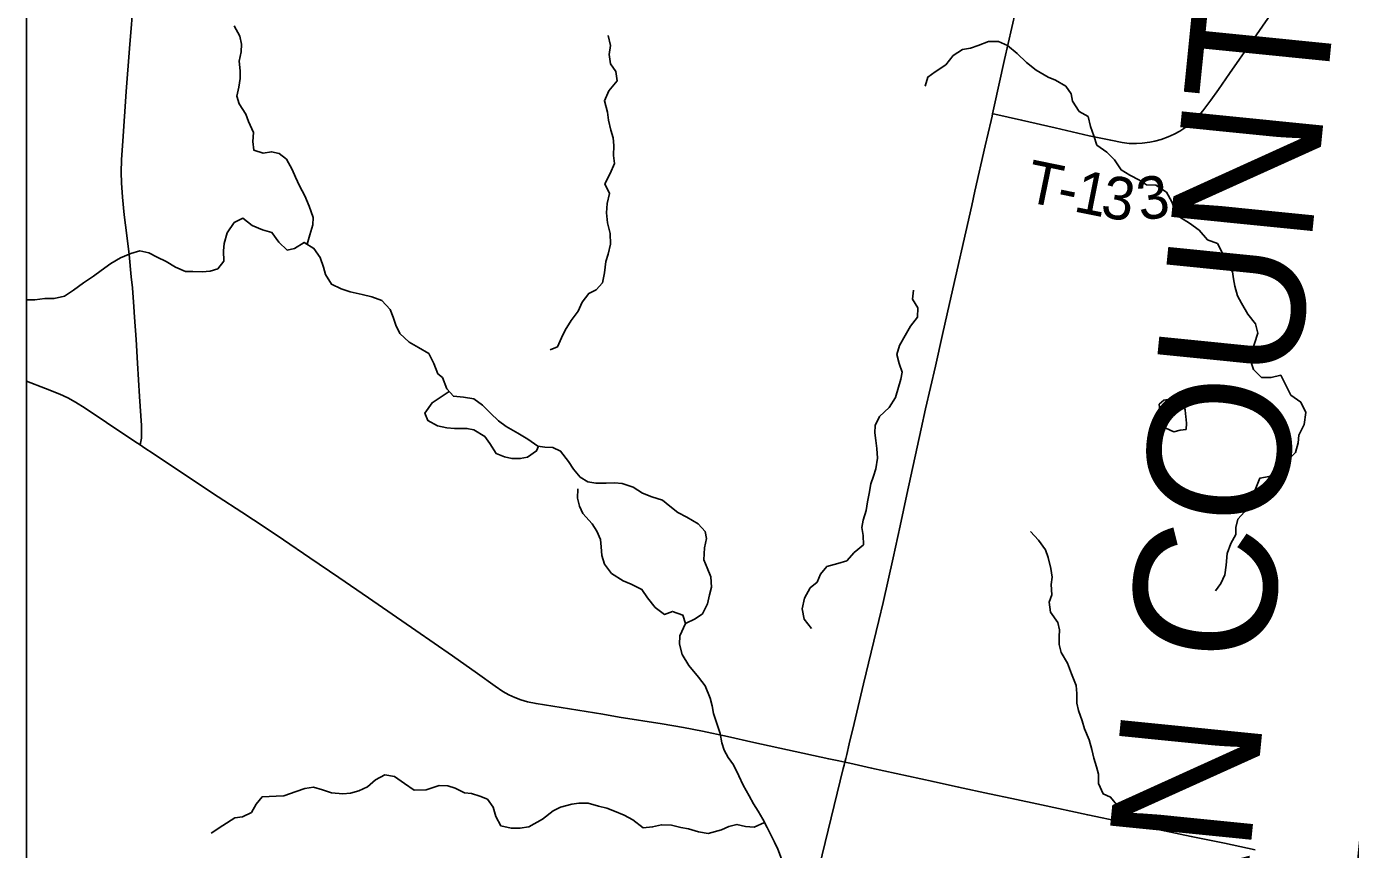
# Model space of a CAD drawing. Extents: x 0 to 34, y 0 to 22.
# Drawn here: x 2.1 to 2.983, y 17.069 to 17.618 of the extents above; entities that cross this region are included whole.
import ezdxf

# ---------------------------------------------------------------- set-up
doc = ezdxf.new("R2010")
doc.units = 0
for name, color, linetype in [('GM_X_Corporation', 7, 'Continuous'), ('GM_X_County_Road', 7, 'Continuous'), ('GM_X_County_Text', 7, 'Continuous'), ('GM_X_Minor_Lake', 7, 'Continuous'), ('GM_X_Minor_River', 7, 'Continuous'), ('GM_X_Township_Road', 7, 'Continuous'), ('GM_X_Township_Road_Text', 7, 'Continuous'), ('SH_Data', 7, 'Continuous')]:
    doc.layers.add(name, color=color, linetype=linetype)

msp = doc.modelspace()

# ---------------------------------------------------------------- linework, layer by layer
at = {"layer": 'GM_X_Corporation'}
msp.add_lwpolyline([(2.84444, 15.57923), (2.89388, 16.10066), (2.90694, 16.23807), (2.9254, 16.40612), (2.98802, 17.06029), (3.03309, 17.51715), (3.06374, 17.81635), (3.09312, 18.12631), (3.11125, 18.30141), (3.1559, 18.76858), (3.1859, 19.03952), (3.22871, 19.50287), (3.24175, 19.64034), (3.25924, 19.82357), (3.29526, 20.15731), (3.35748, 20.79083), (3.36874, 20.9), (2.1, 20.9), (2.1, 14.1)], dxfattribs=at)
msp.add_lwpolyline([(2.1, 18.2085), (2.1, 15.03648), (2.12001, 15.03535), (2.12058, 15.03531), (2.13937, 15.03437), (2.14359, 15.03416), (2.14799, 15.03391), (2.79096, 14.99744), (2.84444, 15.57923), (2.89388, 16.10066), (2.90694, 16.23807), (2.9254, 16.40612), (2.98802, 17.06029), (3.03309, 17.51715), (3.06374, 17.81635), (3.09312, 18.12631), (3.02521, 18.13347), (2.8083, 18.15094), (2.40932, 18.18308), (2.13113, 18.20548)], close=True, dxfattribs=at)
at = {"layer": 'GM_X_County_Road'}
for points in [[(2.646, 17.12758), (2.64664, 17.13014), (2.64729, 17.13271), (2.64891, 17.13983), (2.65233, 17.1535), (2.65855, 17.17984), (2.66879, 17.22211), (2.67158, 17.23422), (2.67824, 17.26393), (2.68289, 17.28518), (2.68747, 17.30613), (2.69687, 17.34986), (2.69984, 17.36321), (2.70644, 17.39185), (2.71106, 17.41291), (2.71586, 17.43349), (2.73069, 17.49888), (2.73282, 17.50844), (2.73952, 17.53879), (2.74354, 17.55552), (2.74419, 17.55846), (2.74455, 17.56011), (2.74542, 17.56404), (2.75258, 17.59636), (2.75994, 17.62834)], [(2.1, 17.38182), (2.11269, 17.37693), (2.12222, 17.37311), (2.12759, 17.3706), (2.1328, 17.36777), (2.13915, 17.36381), (2.15335, 17.35429), (2.17239, 17.34156), (2.17575, 17.33931), (2.17907, 17.3371), (2.1846, 17.3334), (2.21072, 17.31602), (2.22782, 17.3047), (2.24368, 17.29434), (2.25924, 17.28407), (2.27139, 17.27597), (2.28911, 17.26401), (2.30846, 17.25077), (2.32811, 17.23727), (2.35987, 17.21546), (2.38413, 17.19865), (2.40089, 17.18682), (2.41272, 17.17827), (2.41788, 17.17485), (2.42189, 17.17253), (2.42577, 17.17066), (2.42979, 17.16913), (2.43424, 17.1679), (2.44, 17.16675), (2.46238, 17.16311), (2.48447, 17.15956), (2.4955, 17.15773), (2.52402, 17.15314), (2.53843, 17.15074), (2.55094, 17.14829), (2.56766, 17.14472), (2.58525, 17.1408), (2.63532, 17.12984), (2.64203, 17.12842), (2.646, 17.12758), (2.6493, 17.12688), (2.66387, 17.12367), (2.70483, 17.11464), (2.72184, 17.11101), (2.74249, 17.10656), (2.75738, 17.1034), (2.77713, 17.09915), (2.80809, 17.09242), (2.83152, 17.08757), (2.85919, 17.08177), (2.87714, 17.07809), (2.89935, 17.07351), (2.91973, 17.06925)], [(2.62892, 17.05762), (2.64496, 17.12333), (2.64553, 17.12569), (2.646, 17.12758)]]:
    msp.add_lwpolyline(points, dxfattribs=at)
at = {"layer": 'GM_X_Minor_Lake'}
for points in [[(2.87327, 17.3599), (2.87308, 17.36255), (2.87143, 17.36694), (2.8669, 17.36909), (2.86293, 17.36971), (2.85893, 17.369), (2.85567, 17.36638), (2.85618, 17.36239), (2.85575, 17.3584)], [(2.85575, 17.3584), (2.85438, 17.35519), (2.85413, 17.35102), (2.85656, 17.34814), (2.86019, 17.35037), (2.86548, 17.34802), (2.86967, 17.3491), (2.87366, 17.34962), (2.87391, 17.3538), (2.8734, 17.35817), (2.87327, 17.3599)]]:
    msp.add_lwpolyline(points, dxfattribs=at)
at = {"layer": 'GM_X_Minor_River'}
for points in [[(2.28716, 17.47311), (2.28906, 17.47939), (2.29104, 17.486), (2.2913, 17.49094), (2.28856, 17.49838), (2.28582, 17.50543), (2.28212, 17.51194), (2.27956, 17.51786), (2.27735, 17.52282), (2.27347, 17.52971), (2.2686, 17.53357), (2.26351, 17.53478), (2.25782, 17.53372), (2.2516, 17.5359), (2.25111, 17.5416), (2.25138, 17.54767), (2.24808, 17.55492), (2.24625, 17.55988), (2.24181, 17.56678), (2.24036, 17.57192), (2.24158, 17.57779), (2.24261, 17.58366), (2.24249, 17.58878), (2.24182, 17.59524), (2.24323, 17.6013), (2.24349, 17.60642), (2.24224, 17.61194), (2.23855, 17.61882)], [(2.44946, 17.40257), (2.45422, 17.4046), (2.45695, 17.41063), (2.45948, 17.41572), (2.46336, 17.42212), (2.46799, 17.42851), (2.47072, 17.43435), (2.47515, 17.44017), (2.48011, 17.44257), (2.48434, 17.44744), (2.48576, 17.45407), (2.48661, 17.46146), (2.4882, 17.46656), (2.48962, 17.47318), (2.48933, 17.48021), (2.48773, 17.48725), (2.48706, 17.49409), (2.48753, 17.50016), (2.48895, 17.50697), (2.48582, 17.51328), (2.48951, 17.52025), (2.49225, 17.52704), (2.49156, 17.53218), (2.49185, 17.539), (2.49135, 17.54413), (2.48991, 17.54909), (2.48829, 17.55575), (2.48761, 17.56127), (2.48563, 17.5687), (2.48856, 17.5753), (2.49415, 17.58205), (2.4931, 17.58833), (2.48976, 17.5935), (2.48871, 17.59959), (2.48974, 17.60565), (2.48813, 17.61231)], [(2.93982, 17.38006), (2.93687, 17.38575), (2.93041, 17.38413), (2.92397, 17.38422), (2.91856, 17.38943), (2.91693, 17.39495), (2.91681, 17.39989), (2.91936, 17.40688), (2.92154, 17.41387), (2.91992, 17.41996), (2.9149, 17.42649), (2.91065, 17.43376), (2.90807, 17.43873), (2.90626, 17.44521), (2.90538, 17.44997), (2.90469, 17.45472), (2.90062, 17.46123), (2.89767, 17.46754), (2.89454, 17.47347), (2.88795, 17.47603), (2.88236, 17.48237), (2.87599, 17.48721), (2.8696, 17.4911), (2.86607, 17.49609), (2.86406, 17.50143), (2.86056, 17.50774), (2.85343, 17.5124), (2.84737, 17.51268), (2.84249, 17.51578), (2.8361, 17.5191), (2.83047, 17.5226), (2.82602, 17.52931), (2.82079, 17.5345), (2.81404, 17.53916), (2.81223, 17.54545), (2.80986, 17.55155), (2.80825, 17.55822), (2.80243, 17.56172), (2.79798, 17.56843), (2.79691, 17.57337), (2.79338, 17.57855), (2.78662, 17.58244), (2.78173, 17.58441), (2.77365, 17.58927), (2.7671, 17.5943), (2.76093, 17.60027), (2.75457, 17.60568), (2.74855, 17.60823), (2.74192, 17.60833), (2.73488, 17.60558), (2.72975, 17.60395), (2.72443, 17.60288), (2.71832, 17.59899), (2.71331, 17.59279), (2.70624, 17.58815), (2.70127, 17.58462), (2.69949, 17.57857)], [(2.37447, 17.38664), (2.37173, 17.3936), (2.36841, 17.4001), (2.36146, 17.40418), (2.35527, 17.40787), (2.3491, 17.41346), (2.34633, 17.419), (2.34471, 17.42453), (2.34269, 17.42949), (2.3371, 17.43545), (2.33032, 17.43801), (2.3239, 17.43962), (2.31598, 17.44144), (2.30995, 17.44323), (2.30355, 17.44636), (2.29948, 17.45287), (2.29822, 17.45782), (2.29585, 17.4643), (2.29177, 17.47024), (2.2852, 17.47432), (2.27871, 17.47023), (2.27396, 17.46916), (2.26836, 17.47436), (2.26371, 17.48088), (2.25749, 17.48267), (2.25053, 17.48562), (2.24435, 17.49045), (2.23863, 17.48768), (2.2338, 17.48073), (2.23181, 17.47354), (2.23155, 17.46861), (2.23165, 17.46178), (2.22761, 17.45671), (2.22266, 17.45507), (2.21716, 17.45458), (2.21092, 17.45485), (2.206, 17.45492), (2.19942, 17.45786), (2.19322, 17.46155), (2.1872, 17.46448), (2.18157, 17.46741), (2.17572, 17.46863), (2.16963, 17.46682), (2.16278, 17.46406), (2.15629, 17.46017), (2.14979, 17.45552), (2.14482, 17.45179), (2.13794, 17.44733), (2.13144, 17.44249), (2.12533, 17.4384), (2.11849, 17.43698), (2.11224, 17.43687), (2.10561, 17.43602), (2.1, 17.43593)], [(2.68335, 17.38309), (2.68417, 17.38768), (2.68217, 17.39359), (2.68074, 17.39949), (2.68252, 17.40554), (2.68621, 17.41213), (2.68971, 17.41853), (2.69452, 17.42435), (2.69461, 17.43061), (2.69109, 17.43635), (2.69174, 17.44242)], [(2.37447, 17.38664), (2.37752, 17.38413), (2.38043, 17.37668), (2.3849, 17.37166), (2.39155, 17.37117), (2.39837, 17.36992), (2.40419, 17.36564), (2.40961, 17.36042), (2.41485, 17.3554), (2.4201, 17.35151), (2.42782, 17.34702), (2.43441, 17.34311), (2.44117, 17.33844), (2.44591, 17.33779), (2.45123, 17.33751), (2.45632, 17.33514), (2.46172, 17.32822), (2.46505, 17.32303), (2.46952, 17.31764), (2.4746, 17.31471), (2.4799, 17.31367), (2.48675, 17.31374), (2.49227, 17.31403), (2.4974, 17.31356), (2.50477, 17.31097), (2.51097, 17.30706), (2.51721, 17.30468), (2.52439, 17.30228), (2.52926, 17.2984), (2.53451, 17.29413), (2.54054, 17.29099), (2.54807, 17.28669), (2.55274, 17.28148), (2.5536, 17.27672), (2.55236, 17.27067), (2.55202, 17.26251), (2.55421, 17.25735), (2.55658, 17.25123), (2.55702, 17.24439), (2.55579, 17.23929), (2.55436, 17.23324), (2.55101, 17.22665), (2.54619, 17.22332), (2.53967, 17.2202), (2.53591, 17.21191), (2.53562, 17.20623), (2.5374, 17.19936), (2.54184, 17.19207), (2.54836, 17.18437), (2.55282, 17.17859), (2.5561, 17.17038), (2.55753, 17.16523), (2.55839, 17.16009), (2.5602, 17.15474), (2.56272, 17.14672), (2.56394, 17.14044), (2.56556, 17.13566), (2.56814, 17.13069), (2.57167, 17.12588), (2.57534, 17.1186), (2.57827, 17.11229), (2.58214, 17.1052), (2.58509, 17.09983), (2.58823, 17.09484), (2.59118, 17.08967), (2.59413, 17.08411), (2.5967, 17.07913), (2.59909, 17.07434), (2.60129, 17.06956), (2.60384, 17.06325)], [(2.68335, 17.38309), (2.67982, 17.37078), (2.67552, 17.36421), (2.66914, 17.35825), (2.66618, 17.35222), (2.66609, 17.34729), (2.66676, 17.34215), (2.66743, 17.33682), (2.66789, 17.33036), (2.66662, 17.32336), (2.6652, 17.31845), (2.6634, 17.31317), (2.66215, 17.30673), (2.6611, 17.30125), (2.66023, 17.29538), (2.65822, 17.28896), (2.65737, 17.28404), (2.65823, 17.27871), (2.6585, 17.27263), (2.65232, 17.26742), (2.64728, 17.262), (2.64136, 17.26021), (2.63409, 17.25806), (2.62982, 17.25301), (2.62763, 17.24773), (2.62281, 17.24383), (2.61908, 17.23706), (2.61743, 17.22987), (2.61883, 17.22301), (2.62386, 17.21685)], [(2.93982, 17.38006), (2.94362, 17.37243), (2.95019, 17.36776), (2.95368, 17.36087), (2.9524, 17.35292), (2.94885, 17.34577), (2.94838, 17.34065), (2.94675, 17.33423), (2.94074, 17.32788), (2.93548, 17.32095), (2.92916, 17.31821), (2.92286, 17.31699), (2.91987, 17.30926), (2.91977, 17.30338), (2.91758, 17.29791), (2.91258, 17.29458), (2.90831, 17.28972), (2.90688, 17.28424), (2.90679, 17.2795), (2.90364, 17.27348), (2.90105, 17.26688), (2.90035, 17.25911), (2.89947, 17.25267), (2.8969, 17.24683), (2.89339, 17.24196)], [(2.44172, 17.33836), (2.44035, 17.33522), (2.43419, 17.33096), (2.42942, 17.3301), (2.42391, 17.33019), (2.41899, 17.33122), (2.41332, 17.33341), (2.40925, 17.34012), (2.40573, 17.34493), (2.39858, 17.34922), (2.39384, 17.35025), (2.38566, 17.3502), (2.38054, 17.35067), (2.37428, 17.35191), (2.36788, 17.35544), (2.36588, 17.36041), (2.37056, 17.36735), (2.382, 17.37491)], [(2.53967, 17.2202), (2.53787, 17.22574), (2.53107, 17.22813), (2.52571, 17.22614), (2.51951, 17.2308), (2.5143, 17.23715), (2.5106, 17.24272), (2.50343, 17.24626), (2.49815, 17.24863), (2.49025, 17.25351), (2.48561, 17.25966), (2.48381, 17.26558), (2.48334, 17.27128), (2.48305, 17.27622), (2.48048, 17.28177), (2.47733, 17.28657), (2.47118, 17.29351), (2.46899, 17.29848), (2.46756, 17.30382), (2.46786, 17.30989)], [(2.76991, 17.28151), (2.77532, 17.27572), (2.77996, 17.26919), (2.78158, 17.26422), (2.78354, 17.25679), (2.78439, 17.25108), (2.78373, 17.24615), (2.78418, 17.23931), (2.78238, 17.23441), (2.78322, 17.22775), (2.78804, 17.22083), (2.78928, 17.21587), (2.78901, 17.21113), (2.78892, 17.20601), (2.79035, 17.20067), (2.7946, 17.19376), (2.79713, 17.18651), (2.80023, 17.17867), (2.80071, 17.17353), (2.80078, 17.16689), (2.80184, 17.16213), (2.80438, 17.15525), (2.80599, 17.1499), (2.80909, 17.14245), (2.8107, 17.13616), (2.81211, 17.13025), (2.81391, 17.12452), (2.81516, 17.11956), (2.81524, 17.1133), (2.81835, 17.10641), (2.82325, 17.10423), (2.82828, 17.09807), (2.82971, 17.09273)], [(2.5924, 17.08736), (2.58557, 17.08426), (2.57969, 17.08474), (2.57401, 17.08616), (2.56866, 17.08474), (2.56367, 17.08255), (2.55488, 17.08004), (2.54844, 17.0811), (2.54163, 17.08312), (2.53651, 17.08415), (2.53026, 17.08559), (2.52361, 17.08589), (2.51769, 17.08448), (2.5114, 17.08382), (2.50446, 17.08907), (2.49881, 17.0922), (2.49239, 17.09497), (2.4873, 17.09696), (2.48162, 17.09838), (2.4748, 17.10021), (2.46853, 17.10031), (2.46376, 17.09964), (2.45631, 17.09768), (2.45132, 17.0951), (2.44419, 17.08953), (2.43516, 17.08456), (2.42925, 17.08352), (2.42336, 17.08362), (2.41654, 17.08507), (2.41323, 17.09139), (2.41144, 17.09768), (2.40754, 17.10306), (2.40244, 17.10505), (2.39695, 17.10666), (2.39221, 17.10712), (2.38599, 17.11026), (2.38107, 17.11186), (2.37537, 17.11196), (2.36657, 17.10907), (2.35859, 17.10902), (2.3522, 17.1133), (2.34563, 17.11816), (2.33899, 17.11922), (2.33285, 17.11591), (2.32763, 17.11125), (2.32169, 17.10851), (2.31614, 17.10689), (2.311, 17.10641), (2.3036, 17.1071), (2.29755, 17.1091), (2.2915, 17.11092), (2.28578, 17.11006), (2.28004, 17.10807), (2.27181, 17.10518), (2.26667, 17.10488), (2.25716, 17.10447), (2.25327, 17.0996), (2.25013, 17.09415), (2.24418, 17.09122), (2.23904, 17.09055), (2.23096, 17.08537), (2.22326, 17.08018)]]:
    msp.add_lwpolyline(points, dxfattribs=at)
at = {"layer": 'GM_X_Township_Road'}
for points in [[(2.17575, 17.33931), (2.176, 17.3403), (2.17625, 17.34153), (2.17648, 17.34267), (2.17663, 17.34368), (2.17676, 17.34495), (2.17682, 17.34631), (2.17664, 17.35221), (2.17548, 17.37145), (2.174, 17.39377), (2.17309, 17.40959), (2.17212, 17.42447), (2.17166, 17.43129), (2.17063, 17.44397), (2.16995, 17.4514), (2.16843, 17.46625), (2.16687, 17.47885), (2.16513, 17.49276), (2.16403, 17.5045), (2.16341, 17.51409), (2.16324, 17.52091), (2.16343, 17.52958), (2.1642, 17.54192), (2.16655, 17.57506), (2.16868, 17.60359), (2.17155, 17.63892)], [(2.74455, 17.56011), (2.74611, 17.55977), (2.76397, 17.55588), (2.78636, 17.5507), (2.80907, 17.54547), (2.82337, 17.54242), (2.83102, 17.54099), (2.83567, 17.54038), (2.84069, 17.54029), (2.84446, 17.54048), (2.84943, 17.54112), (2.85282, 17.54177), (2.85704, 17.54299), (2.86173, 17.54473), (2.86574, 17.54648), (2.86958, 17.5486), (2.87351, 17.55119), (2.87699, 17.55385), (2.88003, 17.55657), (2.88219, 17.55884), (2.8848, 17.56196), (2.89028, 17.56909), (2.89528, 17.57627), (2.90265, 17.58705), (2.90939, 17.59658), (2.9172, 17.60767), (2.93013, 17.62658)]]:
    msp.add_lwpolyline(points, dxfattribs=at)
at = {"layer": 'SH_Data'}
msp.add_line((2.1, 20.9), (2.1, 14.1), dxfattribs=at)

# ---------------------------------------------------------------- texts
at = {"layer": 'GM_X_County_Text'}
msp.add_text('LOGAN COUNTY', height=0.094697, rotation=84.2687, dxfattribs=at).set_placement((2.8811, 16.71541))
at = {"layer": 'GM_X_Township_Road_Text'}
for s, rotation, p in [('T', 348.39464, (2.76541, 17.5018)), ('1', 348.78271, (2.79786, 17.49515)), ('3', 350.30908, (2.81584, 17.49159)), ('3', 9.09266, (2.8432, 17.48859)), ('-', 348.466, (2.78626, 17.49751))]:
    msp.add_text(s, height=0.02841, rotation=rotation, dxfattribs=at).set_placement(p)

doc.saveas('drawing.dxf')
